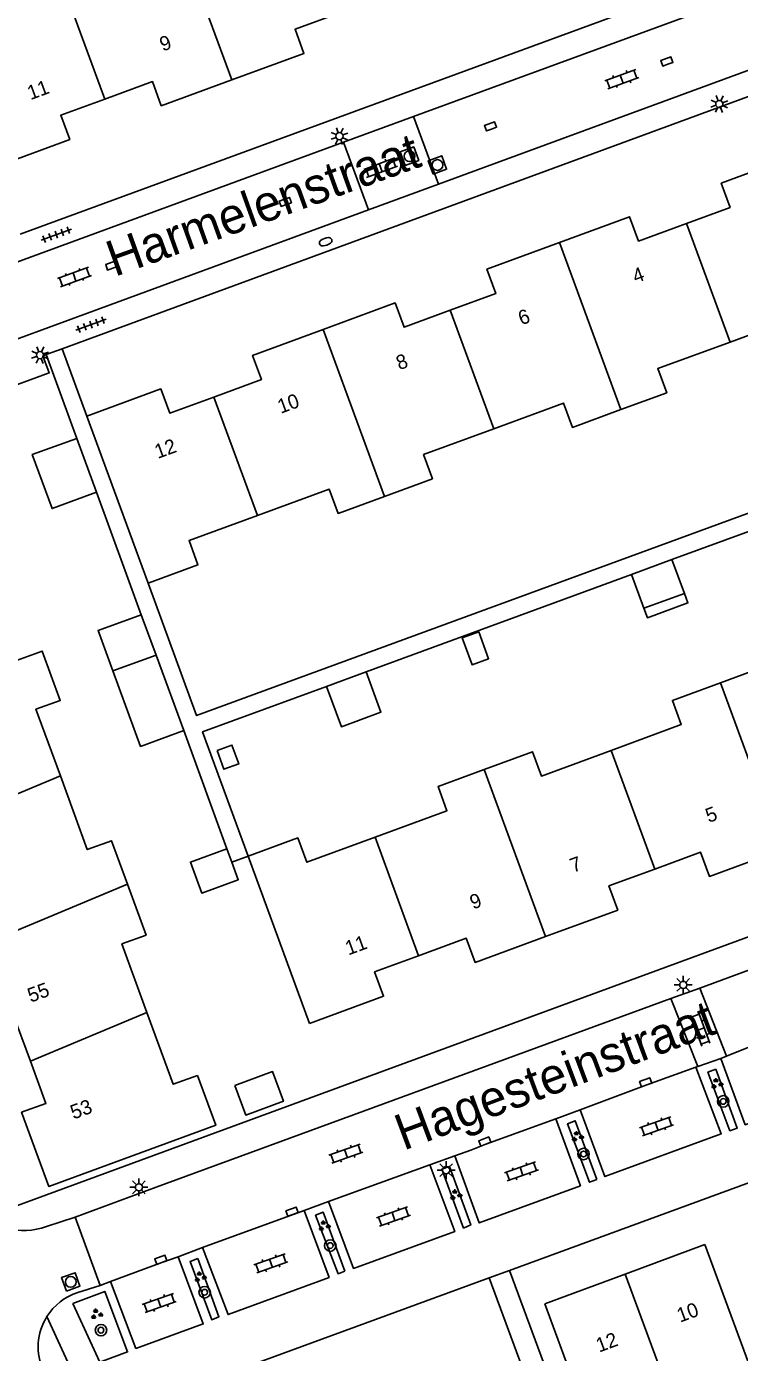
# Model space of a CAD drawing. Extents: x 128000 to 131008, y 398996 to 402500.
# Drawn here: x 128248.8 to 128298.5, y 399087 to 399179.2 of the extents above; entities that cross this region are included whole.
import ezdxf

# ---------------------------------------------------------------- set-up
doc = ezdxf.new("R2010")
doc.units = 0
for name, color, linetype in [('gg-afsc-erfafscheiding', 7, 'Continuous'), ('gg-anno-huisnummerreeks BGT', 7, 'Continuous'), ('gg-anno-openbare ruimte label', 7, 'Continuous'), ('gg-bbg-gedigitaliseerde bebouwing', 7, 'Continuous'), ('gg-bbg-gedigitaliseerde bijgebouw', 7, 'Continuous'), ('gg-bbg-hoofdgebouw', 7, 'Continuous'), ('gg-bbg-luifel en loopbrug', 7, 'Continuous'), ('gg-bbg-tussenscheiding', 7, 'Continuous'), ('gg-knt-verharding', 7, 'Continuous'), ('gg-knt-verharding nz', 7, 'Continuous'), ('gt-grn-weggrens', 7, 'Continuous'), ('gt-symb-boom', 7, 'Continuous'), ('gt-symb-brandkraan', 7, 'Continuous'), ('gt-symb-groenvak', 7, 'Continuous'), ('gt-symb-klinker verharding', 7, 'Continuous'), ('gt-symb-kolk', 7, 'Continuous'), ('gt-symb-lichtmast', 7, 'Continuous'), ('gt-symb-rioolschacht', 7, 'Continuous'), ('gt-symb-tegel verharding', 7, 'Continuous')]:
    doc.layers.add(name, color=color, linetype=linetype)

# ---------------------------------------------------------------- blocks, each defined once
blk = doc.blocks.new('gt0-KL1')
at = {"layer": 'gt-symb-klinker verharding'}
for p, q in [((-1.15, 0.3), (1.15, 0.3)), ((-1, -0.3), (-1, 0.3)), ((-0.5, 0.3), (-0.5, 0.45)), ((0, -0.3), (0, 0.3)), ((0.5, 0.3), (0.5, 0.45)), ((1, -0.3), (1, 0.3)), ((-1.15, -0.3), (1.15, -0.3)), ((-0.5, -0.45), (-0.5, -0.3)), ((0.5, -0.45), (0.5, -0.3))]:
    blk.add_line(p, q, dxfattribs=at)
blk = doc.blocks.new('gt0-GRVAK')
at = {"layer": 'gt-symb-groenvak'}
for p, q in [((-0.11, 0.189), (-0.228, 0.24)), ((-0.182, 0.153), (0.088, 0.153)), ((-0.091, 0.211), (-0.156, 0.322)), ((-0.047, 0.214), (-0.047, 0.393)), ((-0.004, 0.211), (0.061, 0.322)), ((0.015, 0.189), (0.133, 0.24)), ((0.262, -0.052), (0.197, 0.059)), ((0.305, -0.049), (0.305, 0.13)), ((0.349, -0.052), (0.414, 0.059)), ((-0.245, -0.228), (-0.363, -0.177)), ((-0.318, -0.264), (-0.047, -0.264)), ((-0.226, -0.206), (-0.291, -0.095)), ((-0.183, -0.203), (-0.183, -0.024)), ((-0.139, -0.206), (-0.074, -0.095)), ((-0.12, -0.228), (-0.002, -0.177)), ((0.243, -0.074), (0.125, -0.023)), ((0.17, -0.11), (0.441, -0.11)), ((0.368, -0.074), (0.486, -0.023))]:
    blk.add_line(p, q, dxfattribs=at)
blk = doc.blocks.new('gt0-BOOM')
at = {"layer": 'gt-symb-boom'}
for radius in [0.4, 0.2]:
    blk.add_circle((0, 0), radius, dxfattribs=at)
blk = doc.blocks.new('gt0-RS')
at = {"layer": 'gt-symb-rioolschacht'}
blk.add_lwpolyline([(-0.5, -0.5), (0.5, -0.5), (0.5, 0.5), (-0.5, 0.5)], close=True, dxfattribs=at)
blk.add_circle((0, 0), 0.375, dxfattribs=at)
blk = doc.blocks.new('gt0-KOLK')
at = {"layer": 'gt-symb-kolk'}
blk.add_lwpolyline([(0, 0), (0.375, 0), (0.375, 0.4), (-0.375, 0.4), (-0.375, 0), (0, 0)], dxfattribs=at)
blk = doc.blocks.new('gt0-LMAST')
at = {"layer": 'gt-symb-lichtmast'}
for p, q in [((-0.182, 0.173), (-0.447, 0.438)), ((-0.005, 0.246), (-0.005, 0.621)), ((0.172, 0.173), (0.437, 0.438)), ((-0.255, -0.004), (-0.63, -0.004)), ((-0.182, -0.181), (-0.447, -0.446)), ((-0.005, -0.254), (-0.005, -0.629)), ((0.437, -0.446), (0.172, -0.181)), ((0.245, -0.004), (0.62, -0.004))]:
    blk.add_line(p, q, dxfattribs=at)
blk.add_circle((-0.005, -0.004), 0.25, dxfattribs=at)
blk = doc.blocks.new('gt0-BR')
at = {"layer": 'gt-symb-brandkraan'}
for centre, radius, start, end in [((-0.244, 0), 0.206, 107.56694, 252.43307), ((0.599, -2.664), 3, 106.89205, 107.56694), ((0, -0.691), 0.938, 73.10799, 106.89205), ((-0.599, -2.664), 3, 72.43309, 73.10799), ((0.244, 0), 0.206, 287.56695, 72.43309), ((0.599, 2.664), 3, 252.43307, 253.10797), ((0, 0.691), 0.938, 253.10797, 286.89206), ((-0.599, 2.664), 3, 286.89206, 287.56695)]:
    blk.add_arc(centre, radius, start, end, dxfattribs=at)
blk = doc.blocks.new('gt0-TEG1')
at = {"layer": 'gt-symb-tegel verharding'}
for p, q in [((-1.125, 0), (1.125, 0)), ((-0.9, -0.25), (-0.9, 0.25)), ((-0.45, -0.25), (-0.45, 0.25)), ((0, -0.25), (0, 0.25)), ((0.45, -0.25), (0.45, 0.25)), ((0.9, -0.25), (0.9, 0.25))]:
    blk.add_line(p, q, dxfattribs=at)

msp = doc.modelspace()

# ---------------------------------------------------------------- linework, layer by layer
at = {"layer": 'gg-afsc-erfafscheiding'}
for p, q in [((128252.309, 399150.574), (128250.173, 399156.398)), ((128255.594, 399141.616), (128253.686, 399146.818)), ((128255.594, 399141.616), (128256.804, 399138.301)), ((128272.468, 399134.323), (128290.956, 399141.1)), ((128259.76, 399130.229), (128262.768, 399122.011)), ((128263.112, 399121.073), (128264.251, 399121.491)), ((128281.046, 399092.146), (128285.149, 399081.021))]:
    msp.add_line(p, q, dxfattribs=at)
for points in [[(128293.773, 399142.132), (128303.115, 399145.555), (128302.702, 399146.682), (128260.665, 399131.274), (128257.285, 399140.493)], [(128264.251, 399121.491), (128261.078, 399130.148), (128269.713, 399133.313)], [(128285.642, 399079.685), (128287.018, 399080.294), (128282.454, 399092.663)]]:
    msp.add_lwpolyline(points, dxfattribs=at)
at = {"layer": 'gg-bbg-gedigitaliseerde bebouwing'}
for p, q in [((128257.285, 399140.493), (128253.02, 399152.12)), ((128264.251, 399121.491), (128268.52, 399109.86))]:
    msp.add_line(p, q, dxfattribs=at)
for points in [[(128303.294, 399167.673), (128306.625, 399158.593), (128303.156, 399157.32), (128302.537, 399159.008), (128297.819, 399157.277)], [(128297.819, 399157.277), (128292.785, 399155.431), (128293.404, 399153.743), (128290.208, 399152.57)], [(128290.208, 399152.57), (128286.841, 399151.335), (128286.221, 399153.023), (128281.358, 399151.239)], [(128281.358, 399151.239), (128276.47, 399149.446), (128277.089, 399147.758), (128273.747, 399146.532)], [(128273.747, 399146.532), (128270.516, 399145.346), (128269.897, 399147.034), (128264.898, 399145.2)], [(128264.898, 399145.2), (128260.136, 399143.453), (128260.755, 399141.766), (128257.285, 399140.493)], [(128251.17, 399127.086), (128249.473, 399131.72), (128251.161, 399132.339), (128249.904, 399135.772), (128248.122, 399135.12), (128248.06, 399135.288)], [(128305.988, 399134.895), (128300.984, 399133.058), (128300.365, 399134.747), (128297.146, 399133.566)], [(128297.146, 399133.566), (128293.798, 399132.337), (128294.418, 399130.648), (128289.542, 399128.858)], [(128289.542, 399128.858), (128284.672, 399127.071), (128284.052, 399128.76), (128280.699, 399127.529)], [(128255.85, 399119.538), (128254.738, 399122.573), (128253.049, 399121.955), (128251.17, 399127.086)], [(128280.699, 399127.529), (128277.477, 399126.346), (128278.097, 399124.658), (128273.096, 399122.822)], [(128273.096, 399122.822), (128268.341, 399121.077), (128267.721, 399122.765), (128264.251, 399121.491)], [(128257.205, 399110.606), (128255.454, 399115.388), (128257.143, 399116.007), (128255.85, 399119.538)], [(128260.72, 399106.24), (128259.03, 399105.623), (128257.205, 399110.606)], [(128293.797, 399083.515), (128296.227, 399084.41), (128297.091, 399082.065), (128300.205, 399083.213), (128296.06, 399094.46)], [(128284.91, 399090.34), (128289.052, 399079.102), (128292.157, 399080.246), (128291.292, 399082.592), (128293.797, 399083.515)]]:
    msp.add_lwpolyline(points, dxfattribs=at)
at = {"layer": 'gg-bbg-gedigitaliseerde bijgebouw'}
for p, q in [((128290.956, 399141.1), (128293.773, 399142.132)), ((128293.773, 399142.132), (128294.633, 399139.785)), ((128291.817, 399138.752), (128290.956, 399141.1)), ((128294.633, 399139.785), (128291.817, 399138.752)), ((128257.836, 399135.484), (128256.804, 399138.301)), ((128254.832, 399134.383), (128257.836, 399135.484)), ((128269.713, 399133.313), (128272.468, 399134.323)), ((128262.768, 399122.011), (128263.112, 399121.073))]:
    msp.add_line(p, q, dxfattribs=at)
for points in [[(128256.804, 399138.301), (128253.8, 399137.2), (128254.832, 399134.383)], [(128279.158, 399136.689), (128279.846, 399134.811), (128281.001, 399135.235), (128280.313, 399137.112), (128279.158, 399136.689)], [(128272.468, 399134.323), (128273.5, 399131.506), (128270.746, 399130.497), (128269.713, 399133.313)], [(128262.083, 399128.852), (128263.115, 399129.231), (128263.597, 399127.916), (128262.564, 399127.538), (128262.083, 399128.852)], [(128263.112, 399121.073), (128263.559, 399119.851), (128261.024, 399118.922), (128260.233, 399121.082), (128262.768, 399122.011)], [(128263.324, 399105.536), (128265.953, 399106.5), (128266.71, 399104.434), (128264.081, 399103.47), (128263.324, 399105.536)]]:
    msp.add_lwpolyline(points, dxfattribs=at)
at = {"layer": 'gg-bbg-hoofdgebouw'}
for p, q in [((128290.51, 399092.409), (128296.06, 399094.46)), ((128284.91, 399090.34), (128290.51, 399092.409))]:
    msp.add_line(p, q, dxfattribs=at)
for points in [[(128263.106, 399175.517), (128268.14, 399177.36), (128267.52, 399179.05), (128270.714, 399180.221)], [(128254.262, 399174.183), (128257.58, 399175.4), (128258.2, 399173.72), (128263.106, 399175.517)], [(128246.65, 399169.48), (128251.82, 399171.38), (128251.2, 399173.06), (128254.262, 399174.183)], [(128294.791, 399165.529), (128297.82, 399166.64), (128297.2, 399168.33), (128302.358, 399170.225)], [(128285.941, 399164.198), (128290.82, 399165.99), (128291.44, 399164.3), (128294.791, 399165.529)], [(128278.33, 399159.489), (128281.5, 399160.65), (128280.88, 399162.34), (128285.941, 399164.198)], [(128269.48, 399158.159), (128274.49, 399160), (128275.11, 399158.31), (128278.33, 399159.489)], [(128261.872, 399153.447), (128265.18, 399154.66), (128264.56, 399156.35), (128269.48, 399158.159)], [(128253.02, 399152.12), (128258.18, 399154.01), (128258.8, 399152.32), (128261.872, 399153.447)], [(128301.413, 399121.938), (128296.38, 399120.09), (128295.76, 399121.77), (128292.572, 399120.601)], [(128292.572, 399120.601), (128289.38, 399119.43), (128290, 399117.74), (128284.968, 399115.897)], [(128284.968, 399115.897), (128280.06, 399114.1), (128279.44, 399115.78), (128276.126, 399114.565)], [(128244.399, 399114.77), (128246.13, 399110.05), (128247.81, 399110.67), (128249.08, 399107.223)], [(128276.126, 399114.565), (128273.06, 399113.44), (128273.68, 399111.75), (128268.52, 399109.86)], [(128249.08, 399107.223), (128250.16, 399104.29), (128248.47, 399103.67), (128250.36, 399098.51), (128261.99, 399102.77), (128260.72, 399106.24)]]:
    msp.add_lwpolyline(points, dxfattribs=at)
at = {"layer": 'gg-bbg-luifel en loopbrug'}
for p, q in [((128253.686, 399146.818), (128252.309, 399150.574)), ((128257.836, 399135.484), (128259.76, 399130.229))]:
    msp.add_line(p, q, dxfattribs=at)
for points in [[(128253.686, 399146.818), (128250.591, 399145.686), (128249.217, 399149.442), (128252.309, 399150.574)], [(128294.633, 399139.785), (128294.878, 399139.118), (128292.061, 399138.086), (128291.817, 399138.752)], [(128254.832, 399134.383), (128256.754, 399129.129), (128259.76, 399130.229)]]:
    msp.add_lwpolyline(points, dxfattribs=at)
at = {"layer": 'gg-bbg-tussenscheiding'}
for p, q in [((128263.106, 399175.517), (128258.835, 399187.161)), ((128254.262, 399174.183), (128251.227, 399182.457)), ((128294.791, 399165.529), (128297.819, 399157.277)), ((128285.941, 399164.198), (128290.208, 399152.57)), ((128278.33, 399159.489), (128281.358, 399151.239)), ((128269.48, 399158.159), (128273.747, 399146.532)), ((128261.872, 399153.447), (128264.898, 399145.2)), ((128301.413, 399121.938), (128297.146, 399133.566)), ((128292.572, 399120.601), (128289.542, 399128.858)), ((128243.031, 399123.697), (128251.17, 399127.086)), ((128284.968, 399115.897), (128280.699, 399127.529)), ((128276.126, 399114.565), (128273.096, 399122.822)), ((128244.399, 399114.77), (128255.85, 399119.538)), ((128249.08, 399107.223), (128257.205, 399110.606)), ((128290.51, 399092.409), (128293.797, 399083.515))]:
    msp.add_line(p, q, dxfattribs=at)
at = {"layer": 'gg-knt-verharding'}
for p, q in [((128275.763, 399172.967), (128304.467, 399183.493)), ((128306.135, 399178.769), (128277.519, 399168.266)), ((128270.893, 399171.181), (128275.763, 399172.967)), ((128275.763, 399172.967), (128277.519, 399168.266)), ((128243.701, 399161.209), (128270.893, 399171.181)), ((128272.632, 399166.472), (128270.893, 399171.181)), ((128277.519, 399168.266), (128272.632, 399166.472)), ((128272.632, 399166.472), (128245.353, 399156.46)), ((128253.02, 399152.12), (128251.3, 399156.811)), ((128295.703, 399112.316), (128293.697, 399111.593)), ((128297.558, 399107.575), (128295.703, 399112.316)), ((128293.697, 399111.593), (128295.566, 399106.861)), ((128282.454, 399092.663), (128321.385, 399106.935)), ((128295.566, 399106.861), (128295.438, 399106.816)), ((128297.175, 399107.424), (128295.566, 399106.861)), ((128287.381, 399103.85), (128285.674, 399103.222)), ((128278.639, 399100.647), (128276.91, 399100.017)), ((128269.852, 399097.456), (128268.158, 399096.842)), ((128252.202, 399096.38), (128250.209, 399095.72)), ((128253.935, 399091.618), (128252.202, 399096.38)), ((128261.067, 399094.257), (128259.369, 399093.621)), ((128254.671, 399091.889), (128253.935, 399091.618)), ((128252.38, 399091.132), (128253.935, 399091.618))]:
    msp.add_line(p, q, dxfattribs=at)
for points in [[(128297.29, 399184.08), (128297.73, 399182.91), (128248.371, 399164.789)], [(128301.07, 399173.71), (128300.62, 399174.91), (128251.3, 399156.811)], [(128224.15, 399145.49), (128250.4, 399155.13), (128249.96, 399156.32), (128250.173, 399156.398)], [(128295.703, 399112.316), (128333.127, 399126.116), (128343.272, 399129.838)], [(128319.553, 399123.408), (128248.18, 399097.19), (128246.26, 399098.06)], [(128293.697, 399111.593), (128257.855, 399098.465), (128252.202, 399096.38)], [(128295.438, 399106.816), (128297.205, 399102.177), (128289.098, 399099.195), (128287.381, 399103.85)], [(128296.819, 399106.681), (128296.278, 399106.471), (128297.802, 399102.383), (128298.318, 399102.557), (128296.819, 399106.681)], [(128299.356, 399102.979), (128298.878, 399102.802), (128297.175, 399107.424)], [(128285.674, 399103.222), (128287.398, 399098.56), (128280.352, 399095.973), (128278.639, 399100.647)], [(128288.529, 399098.998), (128288.019, 399098.803), (128286.502, 399102.871), (128287.021, 399103.085), (128288.529, 399098.998)], [(128276.91, 399100.017), (128278.643, 399095.362), (128271.59, 399092.804), (128269.852, 399097.456)], [(128278.28, 399099.904), (128277.734, 399099.705), (128279.26, 399095.615), (128279.755, 399095.835), (128278.28, 399099.904)], [(128268.158, 399096.842), (128269.894, 399092.173), (128262.85, 399089.59), (128261.067, 399094.257)], [(128270.991, 399092.618), (128270.513, 399092.429), (128268.948, 399096.514), (128269.482, 399096.714), (128270.991, 399092.618)], [(128254.671, 399091.889), (128256.431, 399087.231), (128261.127, 399088.945), (128259.369, 399093.621)], [(128260.748, 399093.489), (128260.206, 399093.282), (128261.71, 399089.231), (128262.21, 399089.442), (128260.748, 399093.489)], [(128254.25, 399080.73), (128254.95, 399082.58), (128281.046, 399092.146)], [(128252.033, 399090.356), (128254.26, 399091.202), (128255.853, 399086.988), (128253.926, 399086.289), (128252.033, 399090.356)]]:
    msp.add_lwpolyline(points, dxfattribs=at)
for centre, radius, start, end in [((128248.613, 399100.058), 4.622, 254.72282, 290.2015), ((128253.611, 399087.339), 3.987, 107.97656, 148.0054), ((128253.613, 399087.335), 3.992, 147.96666, 204.4778)]:
    msp.add_arc(centre, radius, start, end, dxfattribs=at)
at = {"layer": 'gg-knt-verharding nz'}
for p, q in [((128297.175, 399107.424), (128297.558, 399107.575)), ((128269.852, 399097.456), (128276.91, 399100.017)), ((128261.067, 399094.257), (128268.158, 399096.842))]:
    msp.add_line(p, q, dxfattribs=at)
for points in [[(128297.558, 399107.575), (128299.125, 399108.191), (128304.532, 399110.178)], [(128287.381, 399103.85), (128292.009, 399105.57), (128295.438, 399106.816)], [(128278.639, 399100.647), (128279.756, 399101.043), (128280.803, 399101.45), (128285.674, 399103.222)], [(128254.671, 399091.889), (128258.237, 399093.218), (128259.369, 399093.621)]]:
    msp.add_lwpolyline(points, dxfattribs=at)
at = {"layer": 'gt-grn-weggrens'}
for p, q in [((128251.3, 399156.811), (128250.173, 399156.398)), ((128282.454, 399092.663), (128281.046, 399092.146)), ((128250.229, 399089.452), (128254.25, 399080.73))]:
    msp.add_line(p, q, dxfattribs=at)

# ---------------------------------------------------------------- block references
at = {"layer": 'gt-symb-boom'}
for p in [(128297.343, 399104.429), (128287.615, 399100.767), (128269.971, 399094.392), (128261.221, 399091.144), (128254, 399088.506)]:
    msp.add_blockref('gt0-BOOM', p, dxfattribs=at)
at = {"layer": 'gt-symb-brandkraan', "rotation": 20.120165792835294}
msp.add_blockref('gt0-BR', (128269.652, 399164.254), dxfattribs=at)
at = {"layer": 'gt-symb-groenvak'}
for p in [(128296.876, 399105.653), (128287.159, 399101.974), (128278.687, 399097.915), (128269.532, 399095.756), (128260.897, 399092.198), (128253.677, 399089.617)]:
    msp.add_blockref('gt0-GRVAK', p, dxfattribs=at)
at = {"layer": 'gt-symb-klinker verharding'}
for p, rotation in [((128290.276, 399175.574), 20.120165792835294), ((128273.482, 399169.41), 20.173944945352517), ((128252.157, 399161.801), 20.1201657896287), ((128295.733, 399109.452), 110.24750150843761), ((128292.7, 399102.695), 19.44956876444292), ((128271.064, 399100.79), 19.39552832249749), ((128283.287, 399099.557), 19.44956876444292), ((128274.375, 399096.419), 19.44956876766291), ((128265.84, 399093.156), 19.44956876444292), ((128258.058, 399090.394), 19.44956876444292)]:
    msp.add_blockref('gt0-KL1', p, dxfattribs=dict(at, rotation=rotation))
at = {"layer": 'gt-symb-kolk'}
for p, rotation in [((128293.481, 399176.613), 20.06634962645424), ((128281.201, 399172.092), 20.06634962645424), ((128266.908, 399166.839), 20.06634962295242), ((128254.818, 399162.416), 20.06634962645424), ((128292.009, 399105.57), 20.60969293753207), ((128280.803, 399101.45), 21.28016631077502), ((128267.372, 399096.562), 20.247501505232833), ((128258.237, 399093.218), 20.301249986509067)]:
    msp.add_blockref('gt0-KOLK', p, dxfattribs=dict(at, rotation=rotation))
at = {"layer": 'gt-symb-lichtmast'}
for p, rotation in [((128297.07, 399173.844), 20.066349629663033), ((128270.613, 399171.61), 20.06634962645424), ((128249.757, 399156.372), 20.066349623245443)]:
    msp.add_blockref('gt0-LMAST', p, dxfattribs=dict(at, rotation=rotation))
for p in [(128294.564, 399112.536), (128278.045, 399099.646), (128256.65, 399098.451)]:
    msp.add_blockref('gt0-LMAST', p, dxfattribs=at)
at = {"layer": 'gt-symb-rioolschacht'}
for p, rotation in [((128275.487, 399170.211), 20.120165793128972), ((128277.435, 399169.595), 20.1201657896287), ((128251.895, 399091.865), 20.06634962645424)]:
    msp.add_blockref('gt0-RS', p, dxfattribs=dict(at, rotation=rotation))
at = {"layer": 'gt-symb-tegel verharding', "rotation": 20.120165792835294}
for p in [(128250.884, 399164.746), (128253.299, 399158.485)]:
    msp.add_blockref('gt0-TEG1', p, dxfattribs=at)

# ---------------------------------------------------------------- texts
at = {"layer": 'gg-anno-huisnummerreeks BGT'}
for s, rotation, p in [('9', 20.1, (128258.308, 399177.487)), ('11', 20.2, (128249.09, 399174.106)), ('4', 20.2, (128291.241, 399161.35)), ('6', 20.2, (128283.283, 399158.429)), ('8', 20.1, (128274.779, 399155.31)), ('10', 20.2, (128266.518, 399152.276)), ('12', 20.1, (128257.955, 399149.137)), ('5', 20.2, (128296.329, 399123.8)), ('7', 20.1, (128286.888, 399120.328)), ('9', 20.1, (128279.915, 399117.774)), ('11', 20.1, (128271.232, 399114.582)), ('55', 20.1, (128249.107, 399111.292)), ('53', 20.1, (128252.088, 399103.161)), ('10', 20.3, (128294.334, 399089.024)), ('12', 20.3, (128288.698, 399086.942))]:
    msp.add_text(s, height=1, rotation=rotation, dxfattribs=at).set_placement(p)
at = {"layer": 'gg-anno-openbare ruimte label'}
for s, rotation, p in [('Harmelenstraat', 19.8, (128254.955, 399161.802)), ('Hagesteinstraat', 20.5, (128275.075, 399100.993))]:
    msp.add_text(s, height=2.5, rotation=rotation, dxfattribs=at).set_placement(p)

doc.saveas('drawing.dxf')
